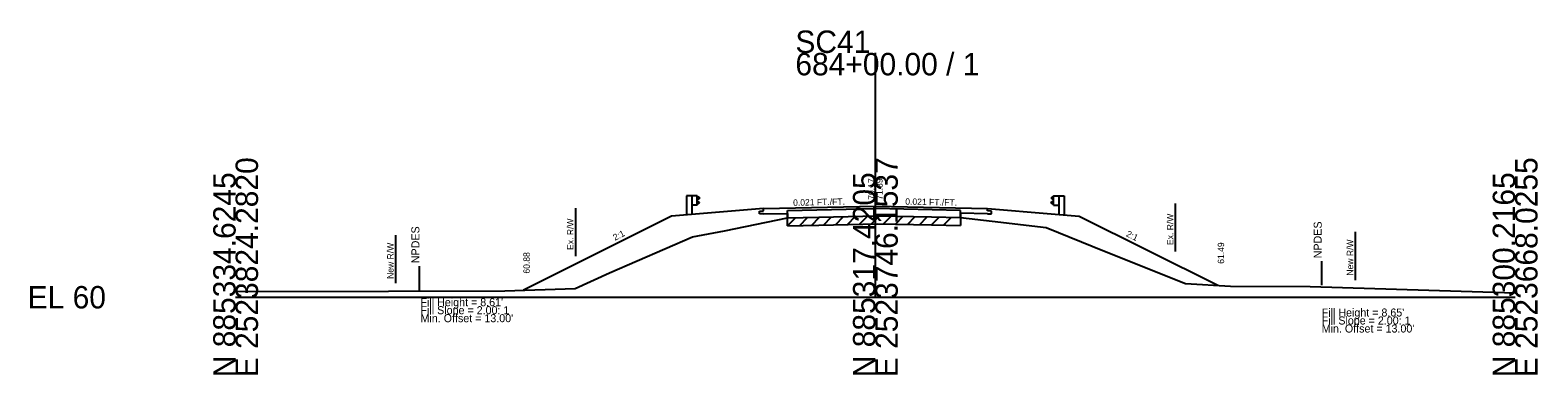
# Model space of a CAD drawing. Extents: x -26 to 183, y -10 to 24021.
# Drawn here: x -25.7 to 162.8, y 13990.3 to 14033.4 of the extents above; entities that cross this region are included whole.
import ezdxf

# ---------------------------------------------------------------- set-up
doc = ezdxf.new("R2010")
doc.units = 0
for name, color, linetype in [('RD_GPK_XS_Cell', 7, 'Continuous'), ('RD_XS_Base', 7, 'Continuous'), ('RD_XS_Buildup', 7, 'Continuous'), ('RD_XS_EarthShd', 7, 'Continuous'), ('RD_XS_ExGround', 7, 'Continuous'), ('RD_XS_ExPaveRet', 7, 'Continuous'), ('RD_XS_ExRW', 7, 'Continuous'), ('RD_XS_GR', 7, 'Continuous'), ('RD_XS_NewRW', 7, 'Continuous'), ('RD_XS_NPDES', 7, 'Continuous'), ('RD_XS_Pave', 7, 'Continuous'), ('RD_XS_TieSlope', 7, 'Continuous'), ('RD_XS_TX_Elev_EX', 7, 'Continuous'), ('RD_XS_TX_Elev_PR', 7, 'Continuous'), ('RD_XS_TX_Slope', 7, 'Continuous'), ('RD_XS_TX_Warning', 7, 'Continuous')]:
    doc.layers.add(name, color=color, linetype=linetype)

msp = doc.modelspace()

# ---------------------------------------------------------------- linework, layer by layer
at = {"layer": 'RD_GPK_XS_Cell'}
for p, q in [((80, 14000), (80, 14030.52)), ((0, 14000), (80, 14000)), ((80, 14000), (160, 14000))]:
    msp.add_line(p, q, dxfattribs=at)
at = {"layer": 'RD_XS_Base'}
for p, q in [((66, 14010.42), (69, 14010.48)), ((69, 14010.48), (69, 14009.9)), ((90.66, 14010.49), (90.66, 14009.95)), ((94, 14010.42), (90.66, 14010.49))]:
    msp.add_line(p, q, dxfattribs=at)
at = {"layer": 'RD_XS_Buildup'}
for p, q in [((69, 14010.84), (80, 14011.07)), ((69, 14009.9), (69, 14010.84)), ((90.66, 14010.85), (80, 14011.07)), ((90.66, 14009.95), (90.66, 14010.85))]:
    msp.add_line(p, q, dxfattribs=at)
at = {"layer": 'RD_XS_EarthShd'}
for p, q in [((58, 14010.43), (54.5, 14010.14)), ((66, 14011.1), (58, 14010.43)), ((94, 14011.1), (102, 14010.43)), ((102, 14010.43), (105.5, 14010.14))]:
    msp.add_line(p, q, dxfattribs=at)
at = {"layer": 'RD_XS_ExGround'}
for p, q in [((61.15, 14008.3), (69, 14009.9)), ((69, 14009.9), (72.93, 14010)), ((72.93, 14010), (80.25, 14010.17)), ((80.25, 14010.17), (87.02, 14010.03)), ((87.02, 14010.03), (90.66, 14009.95)), ((90.66, 14009.95), (94.62, 14009.49)), ((57.12, 14007.56), (61.15, 14008.3)), ((94.62, 14009.49), (101.35, 14008.72)), ((101.35, 14008.72), (108.65, 14005.74)), ((46.77, 14003.06), (57.12, 14007.56)), ((108.65, 14005.74), (118.79, 14001.72)), ((42.45, 14001.11), (46.77, 14003.06)), ((0, 14000.73), (19.13, 14000.74)), ((19.13, 14000.74), (33.65, 14000.8)), ((33.65, 14000.8), (42.45, 14001.11)), ((118.79, 14001.72), (124.42, 14001.39)), ((124.42, 14001.39), (134.38, 14001.32)), ((134.38, 14001.32), (160, 14000.53))]:
    msp.add_line(p, q, dxfattribs=at)
at = {"layer": 'RD_XS_ExPaveRet'}
for p, q in [((69, 14008.9), (70.03, 14009.93)), ((69, 14008.9), (69, 14009.9)), ((70.5, 14008.94), (71.53, 14009.96)), ((72, 14008.97), (73.03, 14010)), ((73.5, 14009.01), (74.52, 14010.04)), ((75, 14009.05), (76.02, 14010.07)), ((76.5, 14009.08), (77.52, 14010.11)), ((78, 14009.12), (79.02, 14010.14)), ((79.5, 14009.16), (80.51, 14010.17)), ((81, 14009.16), (81.98, 14010.14)), ((82.5, 14009.13), (83.48, 14010.11)), ((84, 14009.09), (84.98, 14010.07)), ((85.5, 14009.06), (86.48, 14010.04)), ((87, 14009.03), (87.98, 14010.01)), ((88.5, 14009), (89.48, 14009.98)), ((90.66, 14009.95), (90.66, 14008.95)), ((69, 14008.9), (72.93, 14009)), ((72.93, 14009), (80.25, 14009.17)), ((80.25, 14009.17), (87.02, 14009.03)), ((87.02, 14009.03), (90.66, 14008.95))]:
    msp.add_line(p, q, dxfattribs=at)
at = {"layer": 'RD_XS_ExRW'}
for p, q in [((42.5, 14011.13), (42.5, 14005.13)), ((117.5, 14011.73), (117.5, 14005.73))]:
    msp.add_line(p, q, dxfattribs=at)
at = {"layer": 'RD_XS_GR'}
for p, q in [((56.4, 14012.68), (56.4, 14010.3)), ((57.06, 14012.68), (56.4, 14012.68)), ((57.06, 14012.68), (57.06, 14010.35)), ((57.73, 14012.68), (57.06, 14012.68)), ((57.73, 14011.51), (57.73, 14012.68)), ((57.73, 14012.61), (58, 14012.41)), ((58, 14012.36), (57.73, 14012.16)), ((58, 14011.84), (57.73, 14012.04)), ((57.73, 14011.59), (58, 14011.79)), ((58, 14012.41), (58, 14012.36)), ((58, 14011.79), (58, 14011.84)), ((102.27, 14012.61), (102, 14012.41)), ((102, 14012.41), (102, 14012.36)), ((102, 14012.36), (102.27, 14012.16)), ((102, 14011.84), (102.27, 14012.04)), ((102, 14011.79), (102, 14011.84)), ((102.27, 14011.59), (102, 14011.79)), ((102.27, 14011.51), (102.27, 14012.68)), ((102.27, 14012.68), (102.94, 14012.68)), ((102.94, 14012.68), (102.94, 14010.35)), ((102.94, 14012.68), (103.6, 14012.68)), ((103.6, 14012.68), (103.6, 14010.3)), ((57.73, 14011.51), (57.06, 14011.51)), ((102.27, 14011.51), (102.94, 14011.51))]:
    msp.add_line(p, q, dxfattribs=at)
at = {"layer": 'RD_XS_NewRW'}
for p, q in [((140, 14008.15), (140, 14002.15)), ((20, 14007.74), (20, 14001.74))]:
    msp.add_line(p, q, dxfattribs=at)
at = {"layer": 'RD_XS_NPDES'}
for p, q in [((135.81, 14001.49), (135.81, 14004.49)), ((22.98, 14000.88), (22.98, 14003.88))]:
    msp.add_line(p, q, dxfattribs=at)
at = {"layer": 'RD_XS_Pave'}
for p, q in [((65.5, 14010.77), (66, 14010.78)), ((65.5, 14010.41), (65.5, 14010.77)), ((66, 14010.42), (65.5, 14010.41)), ((66, 14011.1), (80, 14011.39)), ((66, 14010.78), (66, 14011.1)), ((80, 14011.39), (94, 14011.1)), ((94, 14010.78), (94, 14011.1)), ((94.5, 14010.77), (94, 14010.78)), ((94, 14010.42), (94.5, 14010.41)), ((94.5, 14010.41), (94.5, 14010.77))]:
    msp.add_line(p, q, dxfattribs=at)
at = {"layer": 'RD_XS_TieSlope'}
for p, q in [((54.5, 14010.14), (35.98, 14000.88)), ((105.5, 14010.14), (122.81, 14001.49))]:
    msp.add_line(p, q, dxfattribs=at)

# ---------------------------------------------------------------- texts
at = {"layer": 'RD_GPK_XS_Cell'}
for s, p in [('SC41', (70, 14030.52)), ('684+00.00 / 1', (70, 14027.72)), ('EL 60', (-26, 13998.6))]:
    msp.add_text(s, height=2.8, dxfattribs=at).set_placement(p)
for s, p in [('E 2523824.2820', (2.8, 13990)), ('E 2523746.1537', (82.8, 13990)), ('E 2523668.0255', (162.8, 13990)), ('N 885334.6245', (0, 13990)), ('N 885317.4205', (80, 13990)), ('N 885300.2165', (160, 13990))]:
    msp.add_text(s, height=2.8, rotation=90, dxfattribs=at).set_placement(p)
at = {"layer": 'RD_XS_ExRW'}
for p in [(117.25, 14006.52), (42.25, 14005.91)]:
    msp.add_text('Ex. R/W ', height=0.8, rotation=90, dxfattribs=at).set_placement(p)
at = {"layer": 'RD_XS_NewRW'}
for p in [(19.75, 14002.29), (139.75, 14002.7)]:
    msp.add_text('New R/W ', height=0.8, rotation=90, dxfattribs=at).set_placement(p)
at = {"layer": 'RD_XS_TX_Elev_EX'}
msp.add_text('70.17', height=0.8, rotation=90, dxfattribs=at).set_placement((79.9, 14012.17))
at = {"layer": 'RD_XS_TX_Elev_PR'}
for s, p in [('71.39', (80.9, 14012.17)), ('61.49', (123.61, 14004.18)), ('60.88', (36.78, 14002.95))]:
    msp.add_text(s, height=0.8, rotation=90, dxfattribs=at).set_placement(p)
at = {"layer": 'RD_XS_TX_Slope'}
for s, rotation, p in [('0.021 FT./FT.', 1.1916, (69.72, 14011.42)), ('0.021 FT./FT.', 358.8084, (83.73, 14011.56)), ('2:1', 26.5651, (47.43, 14007.04)), ('2:1', 333.4349, (111.28, 14007.65))]:
    msp.add_text(s, height=0.8, rotation=rotation, dxfattribs=at).set_placement(p)
at = {"layer": 'RD_XS_TX_Warning'}
for p in [(22.98, 14003.88), (135.81, 14004.49)]:
    msp.add_text(' NPDES', height=1, rotation=90, dxfattribs=at).set_placement(p)
for s, p in [("Fill Height = 8.61' ", (23.12, 13998.88)), ('Fill Slope = 2.00: 1', (23.12, 13997.88)), ("Fill Height = 8.65' ", (135.81, 13997.59)), ("Min. Offset = 13.00' ", (23.12, 13996.88)), ('Fill Slope = 2.00: 1', (135.81, 13996.59)), ("Min. Offset = 13.00' ", (135.81, 13995.59))]:
    msp.add_text(s, height=1, dxfattribs=at).set_placement(p)

doc.saveas('drawing.dxf')
